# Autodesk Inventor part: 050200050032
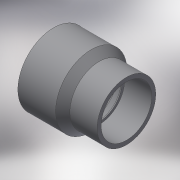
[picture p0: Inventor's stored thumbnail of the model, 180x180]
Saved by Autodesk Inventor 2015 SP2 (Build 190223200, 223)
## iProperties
Created: 2017-10
Part Number: 050200050032
Material: Generic
Description: PLASSON REDUCING SOCKET M.F.50(40)32 CEMENTED
Document SubType Name: Modeling
Designer: KIM
Density: 1 g/cm^3
Appearance: Default
Author: KIM
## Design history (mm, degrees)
derived "050200.ipt"
feature "Solid1::050200.ipt"
tag "TaggingFeature1"
body "Solid1"
other parameters: "d0" = 65, "d1" = 33, "d2" = 22, "d3" = 26, "d4" = 32, "d8" = 28.8, "d9" = 45 deg, "d12" = 0.4, "d_1" = 32, "L_" = 33, "l_" = 26, "l_1" = 22, "H_" = 65, "d11" = 4.63648
